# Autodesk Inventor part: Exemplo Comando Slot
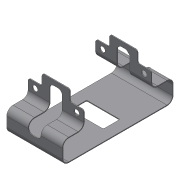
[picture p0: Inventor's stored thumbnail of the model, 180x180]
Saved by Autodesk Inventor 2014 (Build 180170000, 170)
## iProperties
Created: 2013-03
Part Number: Exemplo Comando Slot
Material: Genérico
Document SubType Name: Chapa
Designer: Daniel Severino
Density: 1 g/cm^3
Sheet Metal Rule: Padrão_mm
Flat Pattern Width: 10 cm
Flat Pattern Length: 42.2468 cm
Flat Pattern Area: 422.468 cm^2
Sheet Metal Width: 100,000 mm
Sheet Metal Length: 422,468 mm
Sheet Metal Area: 42246,813 mm^2
Appearance: Default
Author: Daniel Severino
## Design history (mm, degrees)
node "Face1"
  sketch "Esboço1"
    geometry: L1 (0, 0)-(100, 0); L2 (100, 0)-(100, 200); L3 (100, 200)-(0, 200); L4 (0, 200)-(0, 0)
    constraints: 8 end point, 2 horizontal, 2 vertical
    dimensions: "d11" = 200 distance of L3.end L1.start; "d12" = 100 distance of L1.start L1.end
node "Flange1"
node "Flange4"
node "Flange5"
sketch "Esboço7"
  geometry: L1 (100, -38.5)-(0, -38.5) reference; L2 (0, -77)-(0, -38.5) reference; L3 (0, -77)-(100, -77) reference; L4 (100, -77)-(100, -38.5) reference; L5 (0, -57)-(25, -57); L6 (25, -57)-(25, -77); L7 (75, -77)-(75, -57); L8 (75, -57)-(100, -57); 1 further point
  constraints: 8 end point, 4 point on line, 2 horizontal
  dimensions: "d53" = 25 distance of L7.end L8.end; "d55" = 25 distance of L5.start L5.end; "d56" = 20 distance of L5.end L6.end; "d57" = 20 distance of L7.start L7.end
extrude "Extrusão1" cut sketch "Esboço7" stored distance "d58" = 10; taper "d59" = 0 deg
feature "Arredondamento de canto1" dims "d60" = 4
sketch "Esboço8"
  geometry: L1 (-80, 94)-(-20, 94); L2 (-20, 94)-(-20, 124); L3 (-20, 124)-(-80, 124); L4 (-80, 124)-(-80, 94); L5 (-80, 94)-(-20, 124); L6 (-20, 94)-(-80, 124); 2 further points
  constraints: 12 end point, 2 midpoint
feature "Recortar1" sketch "Esboço8" dims "d61" = 1.5 (= Espessura), "d62" = 0
feature "Arredondamento de canto2" dims "d63" = 2
sketch "Esboço9"
  geometry: L1 (0, 0)-(0, 17) reference; L2 (38.419, 68.561)-(61.581, 68.561); L3 (61.581, 68.561)-(61.581, 9.772); L4 (61.581, 9.772)-(38.419, 9.772); L5 (38.419, 9.772)-(38.419, 68.561); L6 (38.419, 68.561)-(61.581, 9.772); L7 (61.581, 68.561)-(38.419, 9.772); 2 further points
  constraints: 12 end point, 2 horizontal, 2 midpoint, 2 vertical
  dimensions: "d64" = 50 distance from line of point (50, 39.166) L1
extrude "Extrusão2" cut sketch "Esboço9" stored distance "d65" = 90.75; taper "d66" = 0 deg
sketch "Esboço10"
  geometry: C1 r 5 at (-16.5, -30); C2 r 5 at (58.5, -30); 1 further point
  constraints: 2 centre point
extrude "Extrusão3" cut sketch "Esboço10" stored distance "d67" = 10; taper "d68" = 0 deg
feature "Arredondamento de canto3" dims "d69" = 8
feature "Chanfro de canto1" dims "d70" = 6, "d71" = 6, angle "d72" = 45 deg
node "Sólido1"
feature "Placa1" dims "Espessura" = 1.5 (derived)
sketch "Esboço2"
  geometry: L1 through (-50, 0) direction (1, 0); L2 through (0, 20) direction (0, 1); L3 (0, 40)-(-100, 40); L4 (-100, 40)-(-100, 0)
  constraints: 6 end point, 1 horizontal, 1 perpendicular, 1 vertical
feature "Placa2" dims "d1" = 1.5 (= Largura_alívio_de_dobra), "d2" = 0.75 (= Profundidade_alívio_de_dobra), "d3" = 3 (= Remanescente_mínimo), "d4" = 1.5 (= Raio_dobra), "d5" = 40, "d6" = 90 deg, "d7" = 10, "d8" = 6 (= Tamanho_alívio_de_dobra), "d9" = 1.5 (= TamanhoFolga), "d10" = 1.5 (= Tamanho_de_raio_de_Jacobi), "Espessura" = 1.5 (derived), "Folga_entre_junção" = 0.01
feature "Dobra1" dims "d1" = 1.5 (= Largura_alívio_de_dobra), "d2" = 0.75 (= Profundidade_alívio_de_dobra), "d3" = 3 (= Remanescente_mínimo), "d4" = 1.5 (= Raio_dobra), "d5" = 40, "d6" = 90 deg, "d7" = 10, "Espessura" = 1.5 (derived), "Folga_entre_junção" = 0.01
feature "Canto1" dims "d5" = 40, "d6" = 90 deg, "d8" = 6 (= Tamanho_alívio_de_dobra), "d9" = 1.5 (= TamanhoFolga), "d10" = 1.5 (= Tamanho_de_raio_de_Jacobi)
sketch "Esboço5"
  geometry: L1 through (50, 0) direction (-1, 1.36e-32); L2 through (0, -20) direction (-1.34e-32, -1); L3 (0, -40)-(100, -40); L4 (100, -40)-(100, 0)
  constraints: 6 end point, 1 horizontal, 1 perpendicular, 1 vertical
feature "Placa5" dims "d33" = 1.5 (= Largura_alívio_de_dobra), "d34" = 0.75 (= Profundidade_alívio_de_dobra), "d35" = 3 (= Remanescente_mínimo), "d36" = 1.5 (= Raio_dobra), "d37" = 40, "d38" = 90 deg, "d39" = 10, "d40" = 6 (= Tamanho_alívio_de_dobra), "d41" = 1.5 (= TamanhoFolga), "d42" = 1.5 (= Tamanho_de_raio_de_Jacobi), "Espessura" = 1.5 (derived), "Folga_entre_junção" = 0.01
feature "Dobra4" dims "d33" = 1.5 (= Largura_alívio_de_dobra), "d34" = 0.75 (= Profundidade_alívio_de_dobra), "d35" = 3 (= Remanescente_mínimo), "d36" = 1.5 (= Raio_dobra), "d37" = 40, "d38" = 90 deg, "d39" = 10, "Espessura" = 1.5 (derived), "Folga_entre_junção" = 0.01
feature "Canto4" dims "d37" = 40, "d38" = 90 deg, "d40" = 6 (= Tamanho_alívio_de_dobra), "d41" = 1.5 (= TamanhoFolga), "d42" = 1.5 (= Tamanho_de_raio_de_Jacobi)
sketch "Esboço6"
  geometry: L1 through (-50, 0) direction (1, 2.03e-32); L2 through (0, 25) direction (-2.15e-32, 1); L3 (0, 50)-(-100, 50); L4 (-100, 50)-(-100, 0)
  constraints: 6 end point, 1 horizontal, 1 perpendicular, 1 vertical
feature "Placa6" dims "d43" = 1.5 (= Largura_alívio_de_dobra), "d44" = 0.75 (= Profundidade_alívio_de_dobra), "d45" = 3 (= Remanescente_mínimo), "d46" = 1.5 (= Raio_dobra), "d47" = 50, "d48" = 90 deg, "d49" = 10, "d50" = 6 (= Tamanho_alívio_de_dobra), "d51" = 1.5 (= TamanhoFolga), "d52" = 1.5 (= Tamanho_de_raio_de_Jacobi), "Espessura" = 1.5 (derived), "Folga_entre_junção" = 0.01
feature "Dobra5" dims "d43" = 1.5 (= Largura_alívio_de_dobra), "d44" = 0.75 (= Profundidade_alívio_de_dobra), "d45" = 3 (= Remanescente_mínimo), "d46" = 1.5 (= Raio_dobra), "d47" = 50, "d48" = 90 deg, "d49" = 10, "Espessura" = 1.5 (derived), "Folga_entre_junção" = 0.01
feature "Canto5" dims "d47" = 50, "d48" = 90 deg, "d50" = 6 (= Tamanho_alívio_de_dobra), "d51" = 1.5 (= TamanhoFolga), "d52" = 1.5 (= Tamanho_de_raio_de_Jacobi)
node "Contorno projetado1"
feature "Definição1"
other parameters: "FatorK" = 4.4, "Raio_dobra" = 1.5 (= Espessura), "Largura_alívio_de_dobra" = 1.5 (= Espessura), "Profundidade_alívio_de_dobra" = 0.75 (= 0.5 x Espessura), "Tamanho_alívio_de_dobra" = 6 (= 4 x Espessura), "Remanescente_mínimo" = 3 (= 2 x Espessura), "Raiodetransição" = 1.5 (= Raio_dobra), "Tamanho_de_raio_de_Jacobi" = 1.5 (= Raio_dobra), "TamanhoFolga" = 1.5 (= Espessura), "d0" = 1.5 (= Raio_dobra), "Espessura" = 1.5, "Largura_alívio_de_dobra" = 1.5, "Profundidade_alívio_de_dobra" = 0.75, "Raio_dobra" = 1.5, "Raiodetransição" = 1.5, "Remanescente_mínimo" = 3, "TamanhoFolga" = 1.5, "Tamanho_alívio_de_dobra" = 6, "Tamanho_de_raio_de_Jacobi" = 1.5
